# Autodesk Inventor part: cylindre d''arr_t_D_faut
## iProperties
Created: 2011-10
Part Number: cylindre d''arr_t_D_faut
Document SubType Name: Modeling
Designer: Bruno
Author: Bruno
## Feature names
1. Base1
